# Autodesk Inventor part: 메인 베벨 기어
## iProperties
Created: 2014-10
Part Number: 메인 베벨 기어
Material: Steel, Mild
Document SubType Name: Modeling
Designer: KYOUNG IL JANG
Categories: <?xml version="1.0" encoding="UTF-16"?> <MemberInstance><Categories><FamilyTemplate><FamilyTemplateParameter ValueType="xs:double" Id="1" ObjectReferenceKey="da
Mass: 269.583 g
Surface Area: 108.837 cm^2
Volume: 34.2981 cm^3
Density: 7.86 g/cm^3
CustomPartVersion: 1
Author: SeoGD™ [www.esajin.kr]
Revision Number: 1
